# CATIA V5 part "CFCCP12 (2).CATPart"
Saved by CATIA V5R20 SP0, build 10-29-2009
Part number: CFCCP12 (2)
Revision: TUTTO
Definition: NON CONOSCIUTO
Nomenclature: CFCCP12 (2)
Source: Unknown
Bounding box of the stored display mesh (mm): x -60 to 60, y -60 to 60, z -65 to 0
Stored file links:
  C:\Users\Utente\Desktop\IO LAVORO\3D X SITO CF\X 3D SITO CF 27-09-2020\CFCCP\CFCCP12\CFCCP12 (2).CATPart
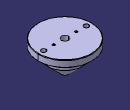
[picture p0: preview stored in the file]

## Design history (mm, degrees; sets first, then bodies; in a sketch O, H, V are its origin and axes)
Body1 "Foro filettato M5-1" (main body)
  Solid1: solid without history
